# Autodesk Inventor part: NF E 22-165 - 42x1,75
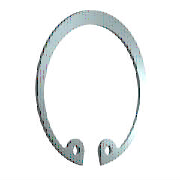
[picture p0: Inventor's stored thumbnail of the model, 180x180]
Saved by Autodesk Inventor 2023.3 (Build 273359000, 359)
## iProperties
Created: 2022-02
Part Number: NF E 22-165 - 42x1,75
Material: Acier, doux
Description: Rondelle élastique d´arrêt
Document SubType Name: Modeling
Standard: NF E 22-165
Designer: Thier
Standards Organization: AFNOR
Language: fr-FR
Size Designation: 42x1,75
Categories: <MemberInstance><Categories><Category DisplayName="Pièces d'arbre" InternalName="7f7aeb1f-a693-4053-b835-cee3144e0d98" Mnemonic="SHFT"><Category DisplayName="An
Density: 7.85 g/cm^3
Appearance: Semi-poli
IsCustomPart: 0
Author: Thier
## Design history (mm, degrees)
sketch "Esquisse1"
  geometry: L1 (0, 15.113)-(0, -73.177) reference; L2 (-45.5, 0)-(45.5, 0) reference; L3 (-4.964, 2.25)-(1.502, 2.25); L4 (0, -1.85)-(-5.307, -1.85); L5 (0, -20)-(-9.868, -39.942); L6 (-9.868, -39.942)-(-23.212, -33.339); L7 (-8.56, -37.298)-(-18.935, -32.164); L8 (-6.319, -38.407)-(-7.565, -40.924); L9 (6.319, -38.407)-(7.565, -40.924); C1 r 1.25 at (-8.56, -37.298); C2 r 1.25 at (8.56, -37.298); A1 r 19.175 centre (0, -21.025) between (13.117, -35.011) and (-13.117, -35.011); A2 r 22.25 centre (0, -20) between (7.565, -40.924) and (-7.565, -40.924); A3 r 2.5 centre (-8.56, -37.298) between (-6.319, -38.407) and (-9.983, -35.243); A4 r 2.5 centre (-11.407, -33.188) between (-13.117, -35.011) and (-9.983, -35.243); A5 r 2.5 centre (11.407, -33.188) between (9.983, -35.243) and (13.117, -35.011); A6 r 2.5 centre (8.56, -37.298) between (9.983, -35.243) and (6.319, -38.407); 3 further points
  constraints: 15 point on circle, 14 end point, 9 symmetric about line, 8 centre point, 6 tangent, 4 coincident, 4 point on line, 3 perpendicular, 1 parallel, 4 other
  dimensions: "d8" = 1.025 distance of A1.centre L5.start (= 0.25 x SRB1); "d38" = 4.1 distance between parallel lines of L4 L3 (= SRB1); "d39" = 20 distance from line of L5.start L2 (= 0.5 x WD); "d43" = 22.25 radius of A2 (= 0.5 x ND); "d45" = 2.95 distance between parallel lines of L7 L6 (= 0.5 x SRB2); "d46" = 2.5 radius of A4 (= SD5); "d47" = 7.565 distance from line of L1 L8.end (= 0.17 x ND); "d48" = 2.5 diameter of C1 (= SD5); "d49" = 2.5 radius of A3 (= SD5)
extrude "Corps" new body sketch "Esquisse1" distance "d2" = 1.75 (= SD); taper "d3" = 0 deg
workaxis "Work Axis1"
workaxis "Work Axis2"
workplane "Work Plane1"
body "Solid1"
other parameters: "SD" = 1.75 [user parameter; used in 1 equation term], "SRB1" = 4.1 [user parameter; used in 2 equation terms], "ND" = 44.5 [user parameter; used in 2 equation terms], "SRB2" = 5.9 [user parameter; used in 1 equation term], "SD5" = 2.5 [user parameter; used in 3 equation terms], "d50" = 0, "d51" = 0, "d52" = 0, "d53" = 0, "SD6" = 45.5 [user parameter], "NND" = 42 [user parameter; used in 1 equation term], "WDMAX" = 42 (= NND) [user parameter]
